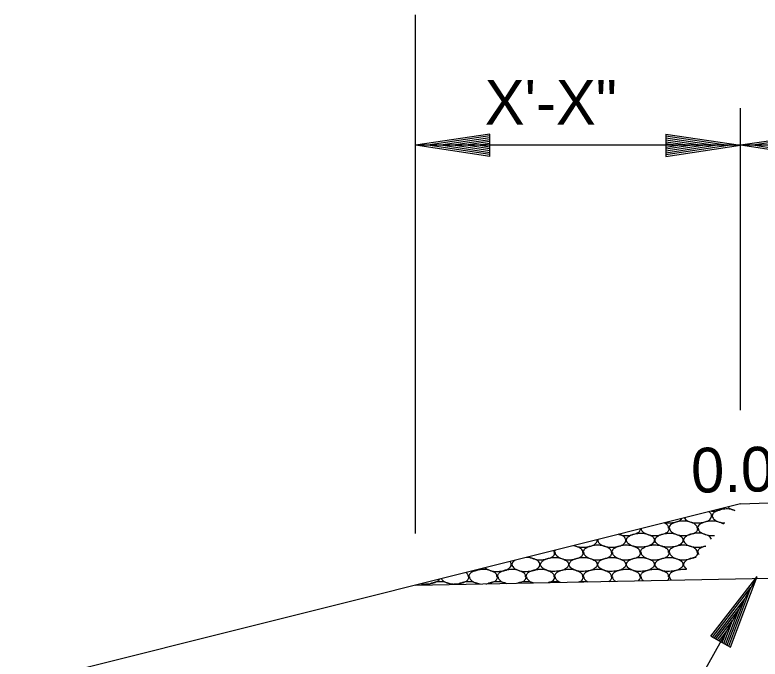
# Model space of a CAD drawing. Extents: x 138 to 3619, y -519 to 1449.
# Drawn here: x 360.6 to 460.6, y -349.7 to -263.3 of the extents above; entities that cross this region are included whole.
import ezdxf

# ---------------------------------------------------------------- set-up
doc = ezdxf.new("R2010")
doc.units = 0
doc.layers.add('R_Annotation', color=7, linetype='Continuous')
doc.layers.add('R_Dimension', color=7, linetype='Continuous')

msp = doc.modelspace()

# ---------------------------------------------------------------- linework, layer by layer
at = {"layer": 'R_Annotation'}
for q in [(498, -327.31), (258, -378.91)]:
    msp.add_line((458, -328.91), q, dxfattribs=at)
msp.add_lwpolyline([(414.37, -339.82), (498, -338.15), (498, -327.31)], dxfattribs=at)
at = {"layer": 'R_Dimension'}
for p, q in [((414.37, -332.86), (414.37, -263.28)), ((414.37, -332.86), (414.37, -275.78)), ((458, -316.31), (458, -275.78)), ((424.37, -279.28), (414.37, -280.78)), ((424.37, -279.53), (416.04, -280.78)), ((424.37, -279.79), (417.76, -280.78)), ((424.37, -280.04), (419.42, -280.78)), ((424.37, -282.28), (424.37, -279.28)), ((448, -279.28), (458, -280.78)), ((448, -279.28), (448, -282.28)), ((448, -279.53), (456.33, -280.78)), ((448, -279.79), (454.61, -280.78)), ((448, -280.04), (452.95, -280.78)), ((468, -279.28), (458, -280.78)), ((468, -279.53), (459.67, -280.78)), ((801.63, -280.78), (414.37, -280.78)), ((424.37, -282.28), (414.37, -280.78)), ((424.37, -282.03), (416.04, -280.78)), ((424.37, -281.78), (417.76, -280.78)), ((424.37, -281.53), (419.42, -280.78)), ((424.37, -280.29), (421.12, -280.78)), ((424.37, -281.27), (421.12, -280.78)), ((424.37, -280.55), (422.79, -280.78)), ((424.37, -281.02), (422.79, -280.78)), ((448, -280.3), (451.25, -280.78)), ((448, -280.55), (449.58, -280.78)), ((448, -282.28), (458, -280.78)), ((448, -281.27), (451.25, -280.78)), ((448, -281.78), (454.61, -280.78)), ((448, -282.03), (456.33, -280.78)), ((448, -281.53), (452.95, -280.78)), ((448, -281.02), (449.58, -280.78)), ((468, -282.28), (458, -280.78)), ((468, -282.03), (459.67, -280.78)), ((454.03, -346.66), (460.22, -338.67)), ((456.65, -348.13), (460.22, -338.67)), ((454.25, -346.79), (459.41, -340.12)), ((456.43, -348.01), (459.41, -340.12)), ((454.47, -346.91), (458.57, -341.63)), ((456.21, -347.88), (458.57, -341.63)), ((454.69, -347.03), (457.76, -343.08)), ((455.99, -347.76), (457.76, -343.08)), ((454.92, -347.16), (456.93, -344.56)), ((455.77, -347.63), (456.93, -344.56)), ((455.14, -347.28), (456.11, -346.02)), ((455.55, -347.51), (456.11, -346.02)), ((454.03, -346.66), (456.65, -348.13))]:
    msp.add_line(p, q, dxfattribs=at)
msp.add_lwpolyline([(419.8, -394.88), (428.78, -394.88), (460.09, -338.91)], dxfattribs=at)
for points in [[(450.47, -330.8), (450.5, -330.85), (450.61, -330.99), (450.87, -331.16), (451.31, -331.35), (451.8, -331.47), (452.3, -331.46), (452.75, -331.42), (453.1, -331.37), (453.42, -331.29), (453.72, -331.12), (453.95, -330.95), (454.11, -330.71), (454.13, -330.5), (454.08, -330.29), (453.93, -330.08), (453.85, -330.02), (453.77, -329.97)], [(454.09, -329.89), (454.11, -329.89), (454.14, -329.89), (454.16, -329.89)], [(454.16, -329.89), (454.18, -329.89), (454.37, -329.89), (454.73, -329.86), (455.21, -329.72), (455.52, -329.62), (455.72, -329.53), (455.78, -329.5), (455.84, -329.45)], [(456.08, -329.59), (455.86, -329.59), (455.35, -329.65), (454.9, -329.8), (454.49, -330.02), (454.38, -330.14), (454.22, -330.38), (454.19, -330.6), (454.3, -330.81), (454.49, -331.02), (454.71, -331.16), (455.15, -331.35), (455.58, -331.46), (455.84, -331.47), (455.89, -331.47)], [(457.26, -329.81), (457.25, -329.8), (457.1, -329.75), (456.84, -329.67), (456.46, -329.59), (456.22, -329.58), (456.08, -329.59)], [(456.35, -329.33), (456.36, -329.34), (456.44, -329.43), (456.67, -329.59), (456.97, -329.72), (457.2, -329.79), (457.26, -329.81)], [(447.88, -331.44), (447.95, -331.45), (448.12, -331.47), (448.46, -331.46), (448.91, -331.42), (449.26, -331.37), (449.58, -331.29), (449.85, -331.14), (450.06, -330.98), (450.15, -330.88)], [(448.36, -332.17), (448.36, -332.16), (448.35, -332.03), (448.32, -331.91), (448.15, -331.68), (447.99, -331.58), (447.83, -331.5), (447.77, -331.47)], [(450.28, -331.21), (450.06, -331.21), (449.55, -331.27), (449.1, -331.42), (448.68, -331.64), (448.55, -331.76), (448.42, -332), (448.41, -332.08), (448.4, -332.16), (448.4, -332.16), (448.4, -332.17)], [(450.32, -331.21), (450.31, -331.21), (450.29, -331.21), (450.28, -331.21)], [(452.2, -332.17), (452.2, -332.16), (452.19, -332.03), (452.16, -331.91), (451.99, -331.68), (451.79, -331.56), (451.43, -331.4), (451.08, -331.29), (450.7, -331.21), (450.46, -331.2), (450.32, -331.21)], [(454.12, -331.21), (453.9, -331.21), (453.39, -331.27), (452.94, -331.42), (452.52, -331.64), (452.39, -331.76), (452.26, -332), (452.25, -332.08), (452.24, -332.16), (452.24, -332.16), (452.24, -332.17)], [(454.16, -331.21), (454.15, -331.21), (454.13, -331.21), (454.12, -331.21)], [(455.75, -331.64), (455.71, -331.6), (455.56, -331.53), (455.27, -331.4), (454.92, -331.29), (454.54, -331.21), (454.3, -331.2), (454.16, -331.21)], [(438.85, -333.7), (438.84, -333.73), (438.86, -333.9), (438.94, -334.07), (439.13, -334.27), (439.35, -334.42), (439.79, -334.61), (440.28, -334.72), (440.78, -334.72), (441.23, -334.68), (441.58, -334.62), (441.9, -334.55), (442.2, -334.38), (442.43, -334.2), (442.59, -333.96), (442.61, -333.75), (442.56, -333.54), (442.39, -333.31), (442.19, -333.19), (441.92, -333.07), (441.75, -333.01), (441.69, -332.99)], [(441.67, -333), (441.68, -333), (441.91, -333.07), (442.23, -333.15), (442.55, -333.15), (442.64, -333.14)], [(442.64, -333.14), (442.66, -333.14), (442.85, -333.15), (443.21, -333.12), (443.69, -332.98), (444, -332.87), (444.3, -332.75), (444.43, -332.63), (444.55, -332.4), (444.57, -332.34), (444.57, -332.27)], [(444.56, -332.84), (444.34, -332.84), (443.83, -332.91), (443.38, -333.05), (442.97, -333.28), (442.86, -333.4), (442.7, -333.63), (442.67, -333.86), (442.78, -334.07), (442.97, -334.27), (443.19, -334.42), (443.63, -334.61), (444.12, -334.72), (444.62, -334.72), (445.07, -334.68), (445.42, -334.62), (445.74, -334.55), (446.04, -334.38), (446.27, -334.2), (446.43, -333.96), (446.45, -333.75), (446.4, -333.54), (446.23, -333.31), (446.03, -333.19), (445.67, -333.03), (445.32, -332.93), (444.94, -332.84), (444.7, -332.83), (444.56, -332.84)], [(444.65, -332.25), (444.67, -332.39), (444.82, -332.62), (445.15, -332.84), (445.6, -333.03), (445.98, -333.13), (446.29, -333.15), (446.39, -333.15), (446.48, -333.14)], [(446.48, -333.14), (446.5, -333.14), (446.69, -333.15), (447.05, -333.12), (447.53, -332.98), (447.84, -332.87), (448.14, -332.75), (448.27, -332.63), (448.4, -332.39), (448.42, -332.29), (448.42, -332.18), (448.42, -332.17)], [(448.4, -332.84), (448.18, -332.84), (447.67, -332.91), (447.22, -333.05), (446.81, -333.28), (446.7, -333.4), (446.54, -333.63), (446.51, -333.86), (446.62, -334.07), (446.81, -334.27), (447.03, -334.42), (447.47, -334.61), (447.96, -334.72), (448.46, -334.72), (448.91, -334.68), (449.26, -334.62), (449.58, -334.55), (449.88, -334.38), (450.11, -334.2), (450.27, -333.96), (450.29, -333.75), (450.24, -333.54), (450.07, -333.31), (449.87, -333.19), (449.51, -333.03), (449.16, -332.93), (448.78, -332.84), (448.54, -332.83), (448.4, -332.84)], [(448.49, -332.17), (448.49, -332.18), (448.49, -332.35), (448.59, -332.5), (448.77, -332.69), (448.99, -332.84), (449.44, -333.03), (449.82, -333.13), (450.13, -333.15), (450.23, -333.15), (450.32, -333.14)], [(450.32, -333.14), (450.34, -333.14), (450.53, -333.15), (450.89, -333.12), (451.37, -332.98), (451.68, -332.87), (451.98, -332.75), (452.11, -332.63), (452.24, -332.39), (452.26, -332.29), (452.26, -332.18), (452.26, -332.17)], [(452.24, -332.84), (452.02, -332.84), (451.51, -332.91), (451.06, -333.05), (450.65, -333.28), (450.54, -333.4), (450.38, -333.63), (450.35, -333.86), (450.46, -334.07), (450.65, -334.27), (450.87, -334.42), (451.31, -334.61), (451.8, -334.72), (452.3, -334.72), (452.75, -334.68), (453.1, -334.62), (453.29, -334.58), (453.31, -334.57), (453.33, -334.57)], [(454.1, -333.64), (454.08, -333.57), (453.96, -333.35), (453.71, -333.19), (453.35, -333.03), (453, -332.93), (452.62, -332.84), (452.38, -332.83), (452.24, -332.84)], [(452.33, -332.17), (452.33, -332.18), (452.33, -332.35), (452.43, -332.5), (452.61, -332.69), (452.83, -332.84), (453.28, -333.03), (453.66, -333.13), (453.97, -333.15), (454.07, -333.15), (454.16, -333.14)], [(435.68, -334.49), (435.75, -334.53), (436.04, -334.63), (436.44, -334.72), (436.94, -334.72), (437.39, -334.68), (437.74, -334.62), (438.06, -334.55), (438.36, -334.38), (438.59, -334.2), (438.75, -333.96), (438.76, -333.85), (438.75, -333.75), (438.75, -333.73)], [(454.16, -333.14), (454.18, -333.14), (454.3, -333.14), (454.42, -333.14), (454.52, -333.13)], [(436.84, -335.42), (436.84, -335.42), (436.83, -335.29), (436.8, -335.16), (436.63, -334.93), (436.43, -334.81), (436.07, -334.65), (435.79, -334.57), (435.61, -334.52), (435.58, -334.52)], [(438.76, -334.46), (438.54, -334.46), (438.03, -334.53), (437.58, -334.67), (437.16, -334.9), (437.03, -335.01), (436.9, -335.26), (436.89, -335.33), (436.88, -335.41), (436.88, -335.42), (436.88, -335.42)], [(438.8, -334.46), (438.79, -334.46), (438.77, -334.46), (438.76, -334.46)], [(440.68, -335.42), (440.68, -335.42), (440.67, -335.29), (440.64, -335.16), (440.47, -334.93), (440.27, -334.81), (439.91, -334.65), (439.56, -334.55), (439.18, -334.46), (438.94, -334.45), (438.8, -334.46)], [(442.6, -334.46), (442.38, -334.46), (441.87, -334.53), (441.42, -334.67), (441, -334.9), (440.87, -335.01), (440.74, -335.26), (440.73, -335.33), (440.72, -335.41), (440.72, -335.42), (440.72, -335.42)], [(442.64, -334.46), (442.63, -334.46), (442.61, -334.46), (442.6, -334.46)], [(444.52, -335.42), (444.52, -335.42), (444.51, -335.29), (444.48, -335.16), (444.31, -334.93), (444.11, -334.81), (443.75, -334.65), (443.4, -334.55), (443.02, -334.46), (442.78, -334.45), (442.64, -334.46)], [(446.44, -334.46), (446.22, -334.46), (445.71, -334.53), (445.26, -334.67), (444.84, -334.9), (444.71, -335.01), (444.58, -335.26), (444.57, -335.33), (444.56, -335.41), (444.56, -335.42), (444.56, -335.42)], [(446.48, -334.46), (446.47, -334.46), (446.45, -334.46), (446.44, -334.46)], [(448.36, -335.42), (448.36, -335.42), (448.35, -335.29), (448.32, -335.16), (448.15, -334.93), (447.95, -334.81), (447.59, -334.65), (447.24, -334.55), (446.86, -334.46), (446.62, -334.45), (446.48, -334.46)], [(450.28, -334.46), (450.06, -334.46), (449.55, -334.53), (449.1, -334.67), (448.68, -334.9), (448.55, -335.01), (448.42, -335.26), (448.41, -335.33), (448.4, -335.41), (448.4, -335.42), (448.4, -335.42)], [(450.32, -334.46), (450.31, -334.46), (450.29, -334.46), (450.28, -334.46)], [(452.2, -335.42), (452.2, -335.42), (452.19, -335.29), (452.16, -335.16), (451.99, -334.93), (451.79, -334.81), (451.43, -334.65), (451.08, -334.55), (450.7, -334.46), (450.46, -334.45), (450.32, -334.46)], [(453.33, -334.57), (453.11, -334.62), (452.9, -334.7), (452.52, -334.9), (452.39, -335.01), (452.26, -335.26), (452.25, -335.33), (452.24, -335.41), (452.24, -335.42), (452.24, -335.42)], [(427.7, -336.49), (427.57, -336.57), (427.48, -336.68), (427.34, -336.89), (427.31, -337.11), (427.42, -337.32), (427.61, -337.53), (427.83, -337.67), (428.27, -337.86), (428.76, -337.98), (429.26, -337.97), (429.71, -337.93), (430.06, -337.88), (430.38, -337.8), (430.68, -337.63), (430.91, -337.46), (431.07, -337.22), (431.09, -337.01), (431.04, -336.8), (430.87, -336.57), (430.67, -336.45), (430.31, -336.29), (429.96, -336.18), (429.61, -336.1), (429.39, -336.09), (429.28, -336.09)], [(429.64, -336), (429.67, -336.02), (429.85, -336.13), (430.24, -336.28), (430.62, -336.39), (430.93, -336.4), (431.03, -336.4), (431.12, -336.4)], [(431.12, -336.4), (431.14, -336.4), (431.33, -336.4), (431.69, -336.37), (432.17, -336.23), (432.48, -336.13), (432.78, -336), (432.91, -335.89), (433.04, -335.64), (433.06, -335.54), (433.06, -335.44), (433.06, -335.42)], [(433.04, -336.1), (432.82, -336.1), (432.31, -336.16), (431.86, -336.31), (431.45, -336.53), (431.34, -336.65), (431.18, -336.89), (431.15, -337.11), (431.26, -337.32), (431.45, -337.53), (431.67, -337.67), (432.11, -337.86), (432.6, -337.98), (433.1, -337.97), (433.55, -337.93), (433.9, -337.88), (434.22, -337.8), (434.52, -337.63), (434.75, -337.46), (434.91, -337.22), (434.93, -337.01), (434.88, -336.8), (434.71, -336.57), (434.51, -336.45), (434.15, -336.29), (433.8, -336.18), (433.42, -336.1), (433.18, -336.09), (433.04, -336.1)], [(433, -335.42), (433, -335.42), (432.99, -335.33), (432.98, -335.25), (432.95, -335.18)], [(433.13, -335.13), (433.12, -335.15), (433.06, -335.24), (433.05, -335.33), (433.04, -335.41), (433.04, -335.42), (433.04, -335.42)], [(433.13, -335.42), (433.13, -335.44), (433.13, -335.61), (433.23, -335.75), (433.41, -335.95), (433.63, -336.1), (434.08, -336.28), (434.46, -336.39), (434.77, -336.4), (434.87, -336.4), (434.96, -336.4)], [(434.96, -336.4), (434.98, -336.4), (435.17, -336.4), (435.53, -336.37), (436.01, -336.23), (436.32, -336.13), (436.62, -336), (436.75, -335.89), (436.88, -335.64), (436.9, -335.54), (436.9, -335.44), (436.9, -335.42)], [(436.88, -336.1), (436.66, -336.1), (436.15, -336.16), (435.7, -336.31), (435.29, -336.53), (435.18, -336.65), (435.02, -336.89), (434.99, -337.11), (435.1, -337.32), (435.29, -337.53), (435.51, -337.67), (435.95, -337.86), (436.44, -337.98), (436.94, -337.97), (437.39, -337.93), (437.74, -337.88), (438.06, -337.8), (438.36, -337.63), (438.59, -337.46), (438.75, -337.22), (438.77, -337.01), (438.72, -336.8), (438.55, -336.57), (438.35, -336.45), (437.99, -336.29), (437.64, -336.18), (437.26, -336.1), (437.02, -336.09), (436.88, -336.1)], [(436.97, -335.42), (436.97, -335.44), (436.97, -335.61), (437.07, -335.75), (437.25, -335.95), (437.47, -336.1), (437.92, -336.28), (438.3, -336.39), (438.61, -336.4), (438.71, -336.4), (438.8, -336.4)], [(438.8, -336.4), (438.82, -336.4), (439.01, -336.4), (439.37, -336.37), (439.85, -336.23), (440.16, -336.13), (440.46, -336), (440.59, -335.89), (440.72, -335.64), (440.74, -335.54), (440.74, -335.44), (440.74, -335.42)], [(440.72, -336.1), (440.5, -336.1), (439.99, -336.16), (439.54, -336.31), (439.13, -336.53), (439.02, -336.65), (438.86, -336.89), (438.83, -337.11), (438.94, -337.32), (439.13, -337.53), (439.35, -337.67), (439.79, -337.86), (440.28, -337.98), (440.78, -337.97), (441.23, -337.93), (441.58, -337.88), (441.9, -337.8), (442.2, -337.63), (442.43, -337.46), (442.59, -337.22), (442.61, -337.01), (442.56, -336.8), (442.39, -336.57), (442.19, -336.45), (441.83, -336.29), (441.48, -336.18), (441.1, -336.1), (440.86, -336.09), (440.72, -336.1)], [(440.81, -335.42), (440.81, -335.44), (440.81, -335.61), (440.91, -335.75), (441.09, -335.95), (441.31, -336.1), (441.76, -336.28), (442.14, -336.39), (442.45, -336.4), (442.55, -336.4), (442.64, -336.4)], [(442.64, -336.4), (442.66, -336.4), (442.85, -336.4), (443.21, -336.37), (443.69, -336.23), (444, -336.13), (444.3, -336), (444.43, -335.89), (444.56, -335.64), (444.58, -335.54), (444.58, -335.44), (444.58, -335.42)], [(444.56, -336.1), (444.34, -336.1), (443.83, -336.16), (443.38, -336.31), (442.97, -336.53), (442.86, -336.65), (442.7, -336.89), (442.67, -337.11), (442.78, -337.32), (442.97, -337.53), (443.19, -337.67), (443.63, -337.86), (444.12, -337.98), (444.62, -337.97), (445.07, -337.93), (445.42, -337.88), (445.74, -337.8), (446.04, -337.63), (446.27, -337.46), (446.43, -337.22), (446.45, -337.01), (446.4, -336.8), (446.23, -336.57), (446.03, -336.45), (445.67, -336.29), (445.32, -336.18), (444.94, -336.1), (444.7, -336.09), (444.56, -336.1)], [(444.65, -335.42), (444.65, -335.44), (444.65, -335.61), (444.75, -335.75), (444.93, -335.95), (445.15, -336.1), (445.6, -336.28), (445.98, -336.39), (446.29, -336.4), (446.39, -336.4), (446.48, -336.4)], [(446.48, -336.4), (446.5, -336.4), (446.69, -336.4), (447.05, -336.37), (447.53, -336.23), (447.84, -336.13), (448.14, -336), (448.27, -335.89), (448.4, -335.64), (448.42, -335.54), (448.42, -335.44), (448.42, -335.42)], [(448.4, -336.1), (448.18, -336.1), (447.67, -336.16), (447.22, -336.31), (446.81, -336.53), (446.7, -336.65), (446.54, -336.89), (446.51, -337.11), (446.62, -337.32), (446.81, -337.53), (447.03, -337.67), (447.47, -337.86), (447.96, -337.98), (448.46, -337.97), (448.91, -337.93), (449.26, -337.88), (449.58, -337.8), (449.88, -337.63), (450.11, -337.46), (450.27, -337.22), (450.29, -337.01), (450.24, -336.8), (450.07, -336.57), (449.87, -336.45), (449.51, -336.29), (449.16, -336.18), (448.78, -336.1), (448.54, -336.09), (448.4, -336.1)], [(448.49, -335.42), (448.49, -335.44), (448.49, -335.61), (448.59, -335.75), (448.77, -335.95), (448.99, -336.1), (449.44, -336.28), (449.82, -336.39), (450.13, -336.4), (450.23, -336.4), (450.32, -336.4)], [(450.32, -336.4), (450.34, -336.4), (450.53, -336.4), (450.89, -336.37), (451.37, -336.23), (451.68, -336.13), (451.98, -336), (452.11, -335.89), (452.24, -335.64), (452.26, -335.54), (452.26, -335.44), (452.26, -335.42)], [(452.06, -336.1), (451.9, -336.11), (451.46, -336.18), (451.06, -336.31), (450.65, -336.53), (450.54, -336.65), (450.38, -336.89), (450.35, -337.11), (450.46, -337.32), (450.65, -337.53), (450.72, -337.58), (450.8, -337.63), (450.8, -337.63)], [(452.33, -335.42), (452.33, -335.44), (452.33, -335.53), (452.36, -335.62), (452.4, -335.69)], [(423.73, -337.48), (423.79, -337.54), (424, -337.68), (424.43, -337.86), (424.92, -337.98), (425.42, -337.97), (425.87, -337.93), (426.22, -337.88), (426.54, -337.8), (426.84, -337.63), (427.07, -337.46), (427.23, -337.22), (427.25, -337.01), (427.2, -336.8), (427.1, -336.67), (427.09, -336.66), (427.08, -336.64)], [(423.4, -337.72), (423.18, -337.72), (422.67, -337.78), (422.22, -337.93), (421.8, -338.15), (421.67, -338.27), (421.54, -338.51), (421.53, -338.59), (421.52, -338.67), (421.52, -338.67), (421.52, -338.68)], [(421.89, -337.94), (421.93, -337.94), (422.15, -337.92), (422.38, -337.88), (422.67, -337.81), (422.78, -337.76), (422.88, -337.69)], [(423.44, -337.72), (423.43, -337.72), (423.41, -337.72), (423.4, -337.72)], [(425.32, -338.68), (425.32, -338.67), (425.31, -338.54), (425.28, -338.42), (425.11, -338.19), (424.91, -338.07), (424.55, -337.91), (424.2, -337.8), (423.82, -337.72), (423.58, -337.71), (423.44, -337.72)], [(427.24, -337.72), (427.02, -337.72), (426.51, -337.78), (426.06, -337.93), (425.64, -338.15), (425.51, -338.27), (425.38, -338.51), (425.37, -338.59), (425.36, -338.67), (425.36, -338.67), (425.36, -338.68)], [(427.28, -337.72), (427.27, -337.72), (427.25, -337.72), (427.24, -337.72)], [(429.16, -338.68), (429.16, -338.67), (429.15, -338.54), (429.12, -338.42), (428.95, -338.19), (428.75, -338.07), (428.39, -337.91), (428.04, -337.8), (427.66, -337.72), (427.42, -337.71), (427.28, -337.72)], [(431.08, -337.72), (430.86, -337.72), (430.35, -337.78), (429.9, -337.93), (429.48, -338.15), (429.35, -338.27), (429.22, -338.51), (429.21, -338.59), (429.2, -338.67), (429.2, -338.67), (429.2, -338.68)], [(431.12, -337.72), (431.11, -337.72), (431.09, -337.72), (431.08, -337.72)], [(433, -338.68), (433, -338.67), (432.99, -338.54), (432.96, -338.42), (432.79, -338.19), (432.59, -338.07), (432.23, -337.91), (431.88, -337.8), (431.5, -337.72), (431.26, -337.71), (431.12, -337.72)], [(434.92, -337.72), (434.7, -337.72), (434.19, -337.78), (433.74, -337.93), (433.32, -338.15), (433.19, -338.27), (433.06, -338.51), (433.05, -338.59), (433.04, -338.67), (433.04, -338.67), (433.04, -338.68)], [(434.96, -337.72), (434.95, -337.72), (434.93, -337.72), (434.92, -337.72)], [(436.84, -338.68), (436.84, -338.67), (436.83, -338.54), (436.8, -338.42), (436.63, -338.19), (436.43, -338.07), (436.07, -337.91), (435.72, -337.8), (435.34, -337.72), (435.1, -337.71), (434.96, -337.72)], [(438.76, -337.72), (438.54, -337.72), (438.03, -337.78), (437.58, -337.93), (437.16, -338.15), (437.03, -338.27), (436.9, -338.51), (436.89, -338.59), (436.88, -338.67), (436.88, -338.67), (436.88, -338.68)], [(438.8, -337.72), (438.79, -337.72), (438.77, -337.72), (438.76, -337.72)], [(440.68, -338.68), (440.68, -338.67), (440.67, -338.54), (440.64, -338.42), (440.47, -338.19), (440.27, -338.07), (439.91, -337.91), (439.56, -337.8), (439.18, -337.72), (438.94, -337.71), (438.8, -337.72)], [(442.6, -337.72), (442.38, -337.72), (441.87, -337.78), (441.42, -337.93), (441, -338.15), (440.87, -338.27), (440.74, -338.51), (440.73, -338.59), (440.72, -338.67), (440.72, -338.67), (440.72, -338.68)], [(442.64, -337.72), (442.63, -337.72), (442.61, -337.72), (442.6, -337.72)], [(444.52, -338.68), (444.52, -338.67), (444.51, -338.54), (444.48, -338.42), (444.31, -338.19), (444.11, -338.07), (443.75, -337.91), (443.4, -337.8), (443.02, -337.72), (442.78, -337.71), (442.64, -337.72)], [(446.44, -337.72), (446.22, -337.72), (445.71, -337.78), (445.26, -337.93), (444.84, -338.15), (444.71, -338.27), (444.58, -338.51), (444.57, -338.59), (444.56, -338.67), (444.56, -338.67), (444.56, -338.68)], [(446.48, -337.72), (446.47, -337.72), (446.45, -337.72), (446.44, -337.72)], [(448.36, -338.68), (448.36, -338.67), (448.35, -338.54), (448.32, -338.42), (448.15, -338.19), (447.95, -338.07), (447.59, -337.91), (447.24, -337.8), (446.86, -337.72), (446.62, -337.71), (446.48, -337.72)], [(450.28, -337.72), (450.06, -337.72), (449.55, -337.78), (449.1, -337.93), (448.68, -338.15), (448.55, -338.27), (448.42, -338.51), (448.41, -338.59), (448.4, -338.67), (448.4, -338.67), (448.4, -338.68)], [(450.32, -337.72), (450.31, -337.72), (450.29, -337.72), (450.28, -337.72)], [(450.72, -337.73), (450.59, -337.71), (450.45, -337.71), (450.32, -337.72)], [(415.76, -339.65), (415.78, -339.65), (415.97, -339.66), (416.33, -339.63), (416.81, -339.49), (417.12, -339.38), (417.41, -339.26), (417.53, -339.15), (417.62, -339.01)], [(417.85, -338.95), (417.88, -339.01), (418, -339.16), (418.27, -339.35), (418.72, -339.54), (419.1, -339.64), (419.41, -339.66), (419.51, -339.66), (419.6, -339.65)], [(419.6, -339.65), (419.62, -339.65), (419.81, -339.66), (420.17, -339.63), (420.65, -339.49), (420.96, -339.38), (421.26, -339.26), (421.39, -339.14), (421.52, -338.9), (421.54, -338.8), (421.54, -338.69), (421.54, -338.68)], [(421.48, -338.68), (421.48, -338.67), (421.47, -338.54), (421.44, -338.42), (421.3, -338.23), (421.23, -338.17), (421.16, -338.12)], [(421.61, -338.68), (421.61, -338.69), (421.61, -338.86), (421.71, -339.01), (421.89, -339.2), (422.11, -339.35), (422.53, -339.53), (422.88, -339.63), (423.07, -339.65)], [(423.84, -339.63), (423.89, -339.63), (424.12, -339.59), (424.49, -339.49), (424.8, -339.38), (425.1, -339.26), (425.23, -339.14), (425.36, -338.9), (425.38, -338.8), (425.38, -338.69), (425.38, -338.68)], [(425.45, -338.68), (425.45, -338.69), (425.45, -338.86), (425.55, -339.01), (425.73, -339.2), (425.95, -339.35), (426.25, -339.49), (426.48, -339.56), (426.55, -339.58)], [(428.1, -339.55), (428.18, -339.52), (428.41, -339.46), (428.64, -339.38), (428.94, -339.26), (429.07, -339.14), (429.2, -338.9), (429.22, -338.8), (429.22, -338.69), (429.22, -338.68)], [(429.29, -338.68), (429.29, -338.69), (429.29, -338.86), (429.39, -339.01), (429.57, -339.2), (429.78, -339.35), (430, -339.46), (430.15, -339.51)], [(432.22, -339.46), (432.36, -339.42), (432.67, -339.35), (432.91, -339.14), (433.04, -338.9), (433.06, -338.8), (433.06, -338.69), (433.06, -338.68)], [(433.13, -338.68), (433.13, -338.69), (433.13, -338.86), (433.23, -339.01), (433.41, -339.2), (433.56, -339.31), (433.73, -339.4), (433.81, -339.43)], [(436.31, -339.38), (436.36, -339.36), (436.58, -339.29), (436.75, -339.14), (436.88, -338.9), (436.9, -338.8), (436.9, -338.69), (436.9, -338.68)], [(436.97, -338.68), (436.97, -338.69), (436.97, -338.86), (437.07, -339.01), (437.25, -339.2), (437.35, -339.28), (437.47, -339.34), (437.5, -339.36)], [(440.35, -339.3), (440.48, -339.23), (440.6, -339.12), (440.72, -338.9), (440.74, -338.8), (440.74, -338.69), (440.74, -338.68)], [(440.81, -338.68), (440.81, -338.69), (440.81, -338.86), (440.91, -339.01), (441.08, -339.19), (441.14, -339.24), (441.21, -339.28)], [(444.31, -339.22), (444.39, -339.16), (444.54, -339), (444.58, -338.8), (444.58, -338.69), (444.58, -338.68)], [(444.65, -338.68), (444.65, -338.69), (444.65, -338.86), (444.75, -339.01), (444.89, -339.16), (444.92, -339.19), (444.94, -339.21)], [(448.24, -339.14), (448.28, -339.1), (448.39, -338.96), (448.42, -338.8), (448.42, -338.69), (448.42, -338.68)], [(448.49, -338.68), (448.49, -338.69), (448.49, -338.86), (448.59, -339.01), (448.7, -339.13), (448.7, -339.13), (448.71, -339.13)], [(415.46, -339.8), (415.41, -339.76), (415.31, -339.7), (415.2, -339.65), (415.15, -339.63)], [(415.19, -339.62), (415.28, -339.64), (415.47, -339.66), (415.67, -339.66), (415.76, -339.65)], [(417.68, -339.35), (417.46, -339.35), (416.95, -339.42), (416.5, -339.56), (416.21, -339.72), (416.16, -339.75), (416.12, -339.79)], [(419.19, -339.73), (419.17, -339.72), (419.05, -339.66), (418.79, -339.54), (418.44, -339.44), (418.06, -339.35), (417.82, -339.34), (417.68, -339.35)], [(421.52, -339.35), (421.3, -339.35), (420.79, -339.42), (420.34, -339.56), (420.09, -339.7), (420.08, -339.7), (420.08, -339.71)], [(422.88, -339.65), (422.82, -339.62), (422.6, -339.53), (422.28, -339.44), (421.9, -339.35), (421.66, -339.34), (421.52, -339.35)], [(425.36, -339.35), (425.14, -339.35), (424.69, -339.41), (424.28, -339.53), (424.08, -339.63)], [(426.56, -339.58), (426.54, -339.57), (426.38, -339.52), (426.12, -339.44), (425.74, -339.35), (425.5, -339.34), (425.36, -339.35)], [(429.2, -339.35), (428.98, -339.35), (428.6, -339.4), (428.25, -339.5), (428.12, -339.55)], [(430.18, -339.51), (430.09, -339.48), (429.9, -339.42), (429.58, -339.35), (429.34, -339.34), (429.2, -339.35)], [(433.04, -339.35), (432.82, -339.35), (432.54, -339.39), (432.27, -339.45), (432.22, -339.46)], [(433.77, -339.43), (433.76, -339.43), (433.66, -339.41), (433.42, -339.35), (433.18, -339.34), (433.04, -339.35)], [(436.88, -339.35), (436.76, -339.35), (436.63, -339.36), (436.51, -339.38)], [(437.27, -339.36), (437.14, -339.35), (437.01, -339.34), (436.88, -339.35)]]:
    msp.add_open_spline(points, degree=3, dxfattribs=at)

# ---------------------------------------------------------------- texts
at = {"layer": 'R_Annotation'}
msp.add_text('X\'-X"', height=6, dxfattribs=at).set_placement((423.67, -278.01))
msp.add_text("0.04'/'", height=6, rotation=1.0613, dxfattribs=at).set_placement((451.42, -327.41))

doc.saveas('drawing.dxf')
